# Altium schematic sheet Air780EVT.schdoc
size 363 x 111 mm
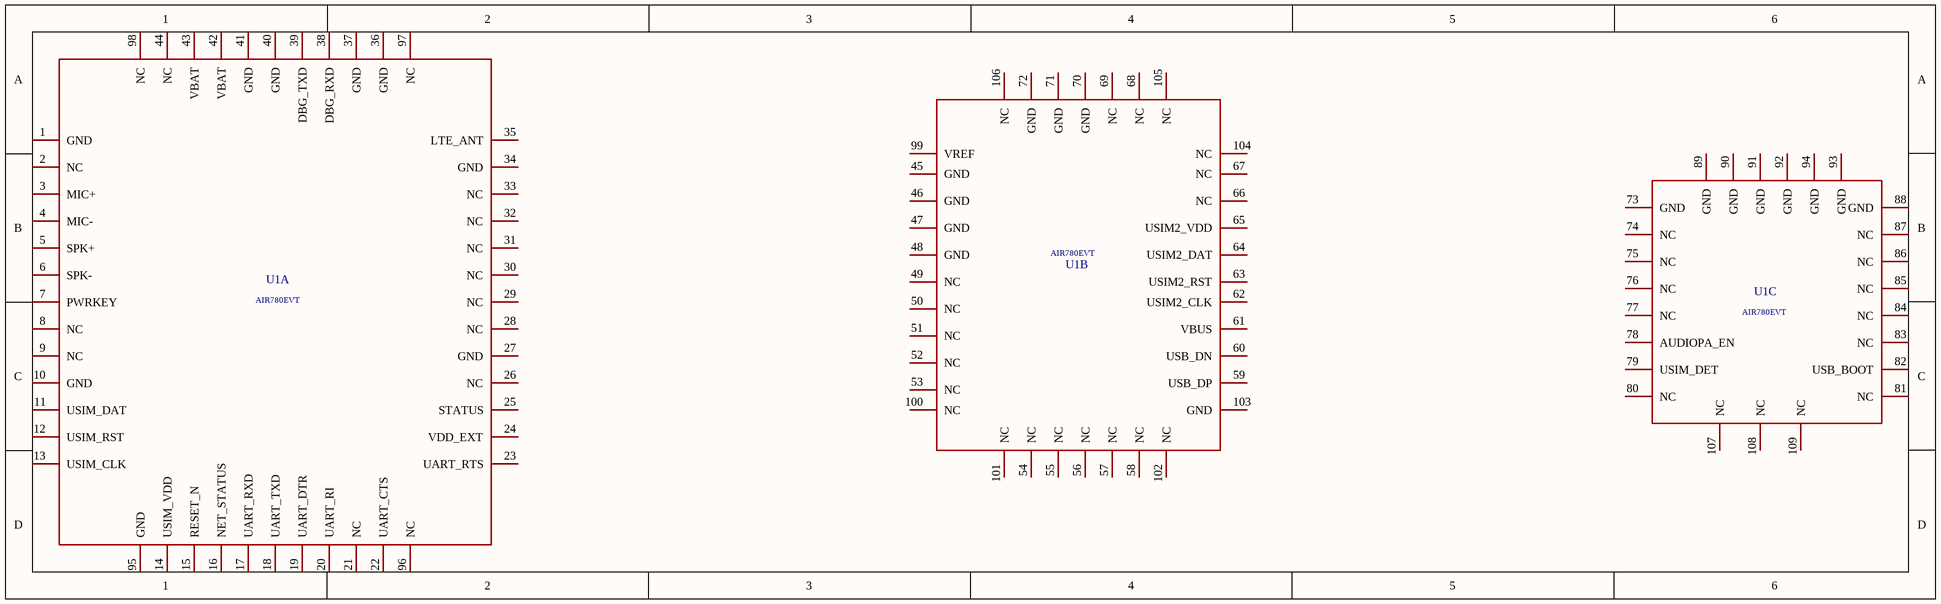
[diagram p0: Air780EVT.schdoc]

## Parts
U1  Air780EHT  (value not drawn)  (parts A,B,C of 3)

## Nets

Not connected (* = marked no-connect by the designer): U1 1(GND) 2(NC) 3(MIC+) 4(MIC-) 5(SPK+) 6(SPK-) 7(PWRKEY) 8(NC) 9(NC) 10(GND) 11(USIM_DAT) 12(USIM_RST) 13(USIM_CLK) 14(USIM_VDD) 15(RESET_N) 16(NET_STATUS) 17(UART_RXD) 18(UART_TXD) 19(UART_DTR) 20(UART_RI) 21(NC) 22(UART_CTS) 23(UART_RTS) 24(VDD_EXT) 25(STATUS) 26(NC) 27(GND) 28(NC) 29(NC) 30(NC) 31(NC) 32(NC) 33(NC) 34(GND) 35(LTE_ANT) 36(GND) 37(GND) 38(DBG_RXD) 39(DBG_TXD) 40(GND) 41(GND) 42(VBAT) 43(VBAT) 44(NC) 45(GND) 46(GND) 47(GND) 48(GND) 49(NC) 50(NC) 51(NC) 52(NC) 53(NC) 54(NC) 55(NC) 56(NC) 57(NC) 58(NC) 59(USB_DP) 60(USB_DN) 61(VBUS) 62(USIM2_CLK) 63(USIM2_RST) 64(USIM2_DAT) 65(USIM2_VDD) 66(NC) 67(NC) 68(NC) 69(NC) 70(GND) 71(GND) 72(GND) 73(GND) 74(NC) 75(NC) 76(NC) 77(NC) 78(AUDIOPA_EN) 79(USIM_DET) 80(NC) 81(NC) 82(USB_BOOT) 83(NC) 84(NC) 85(NC) 86(NC) 87(NC) 88(GND) 89(GND) 90(GND) 91(GND) 92(GND) 93(GND) 94(GND) 95(GND) 96(NC) 97(NC) 98(NC) 99(VREF) 100(NC) 101(NC) 102(NC) 103(GND) 104(NC) 105(NC) 106(NC) 107(NC) 108(NC) 109(NC)

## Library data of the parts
U1 = AIR780EVT: Add into BOM: yes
